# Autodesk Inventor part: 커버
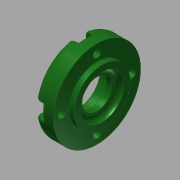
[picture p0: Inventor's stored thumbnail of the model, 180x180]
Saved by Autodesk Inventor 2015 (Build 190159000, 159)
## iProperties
Created: 2015-11
Part Number: 커버
Material: 알루미늄 6061
Document SubType Name: Modeling
Designer: mduedu
Density: 1 g/cm^3
Appearance: 매끄러움 - 짙은 산림 녹색
Author: mduedu
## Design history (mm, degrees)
sketch "스케치1"
  geometry: L1 (-7, 0)-(7, 0); L2 (-7, 0)-(-7, 25); L3 (-7, 25)-(4, 25); L4 (4, 25)-(4, 16); L5 (4, 16)-(7, 16); L6 (7, 16)-(7, 0); 2 further points
  constraints: 12 end point, 3 perpendicular, 2 parallel, 1 coincident, 1 horizontal, 1 midpoint
  dimensions: "d0" = 14 distance of L1.start L1.end; "d1" = 50 diameter of L3 L1; "d2" = 3 distance of L4.end L5.end; "d3" = 32 diameter of L5 L1
revolve "회전1" sketch "스케치1" stored, may be unused: angle "d4" = 90 deg
hole "구멍1" diameter "d7" = 25; stored, may be unused: countersink angle "d11" = 90 deg, drill point angle "d13" = 0 deg; dims "d5" = 10, "d6" = 10, "d8" = 6, "d9" = 4, "d10" = 2, "d12" = 3
hole "구멍2" diameter "d16" = 25; stored, may be unused: countersink angle "d20" = 90 deg, drill point angle "d22" = 0 deg; dims "d17" = 6, "d18" = 4, "d19" = 2, "d21" = 7.7, "d58" = 10, "d59" = 10
hole "구멍3" diameter "d25" = 17; stored, may be unused: countersink angle "d29" = 90 deg, drill point angle "d31" = 0 deg; dims "d23" = 10, "d24" = 10, "d26" = 6, "d27" = 4, "d28" = 2, "d30" = 4.2
chamfer "모따기1" distance "d32" = 0.6; stored, may be unused: second distance "d33" = 2, angle "d34" = 30 deg
fillet "모깎기1" dims "d35" = 0.3
fillet "모깎기2" dims "d36" = 3
fillet "모깎기3" dims "d37" = 3
fillet "모깎기4" dims "d38" = 0.3
sketch "스케치2" dims "d39" = 40
  geometry: 6 further points
  constraints: 2 vertical alignment, 1 coincident, 7 other
  dimensions: "d42" = 360 deg dimension on point (0, 0) point (0, 20) (derived)
sketch "스케치3"
  geometry: 4 further points
hole "구멍4" sketch "스케치3" at (-20, 0), (0, -20), (20, 0), (0, 20) diameter "d44" = 4.5; stored, may be unused: countersink angle "d48" = 90 deg, drill point angle "d50" = 0 deg; dims "d45" = 6, "d46" = 8, "d47" = 4.6, "d49" = 8
sketch "스케치4"
  geometry: L1 (-4, 0)-(-4, -4.678); L2 (4, 0)-(4, -4.678); A1 r 4 centre (0, 0) between (3.621, -1.7) and (-3.621, -1.7) reference; A2 r 25 centre (0, 20) between (-4, -4.678) and (4, -4.678) reference; 1 further point
  constraints: 4 end point, 4 point on circle, 2 tangent, 1 parallel, 1 vertical
extrude "돌출1" cut sketch "스케치4" stored distance "d51" = 0; taper "d52" = 0 deg
fillet "모깎기5" dims "d56" = 0.3
fillet "모깎기6" dims "d57" = 1
node "솔리드1"
pattern_circular "원형 패턴1" dims angle "d54" = 360 deg
